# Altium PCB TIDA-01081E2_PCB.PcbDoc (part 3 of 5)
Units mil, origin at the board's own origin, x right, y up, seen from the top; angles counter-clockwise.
Board outline 8611.33 x 3169.64 mil, 4 copper layers (Top Layer, VCC, GND, Bottom Layer), stack 61.6 mil thick; 411 components, 187 nets, 1087 pads, 1987 vias.
Unrouted connection lines stored in the file: 7.
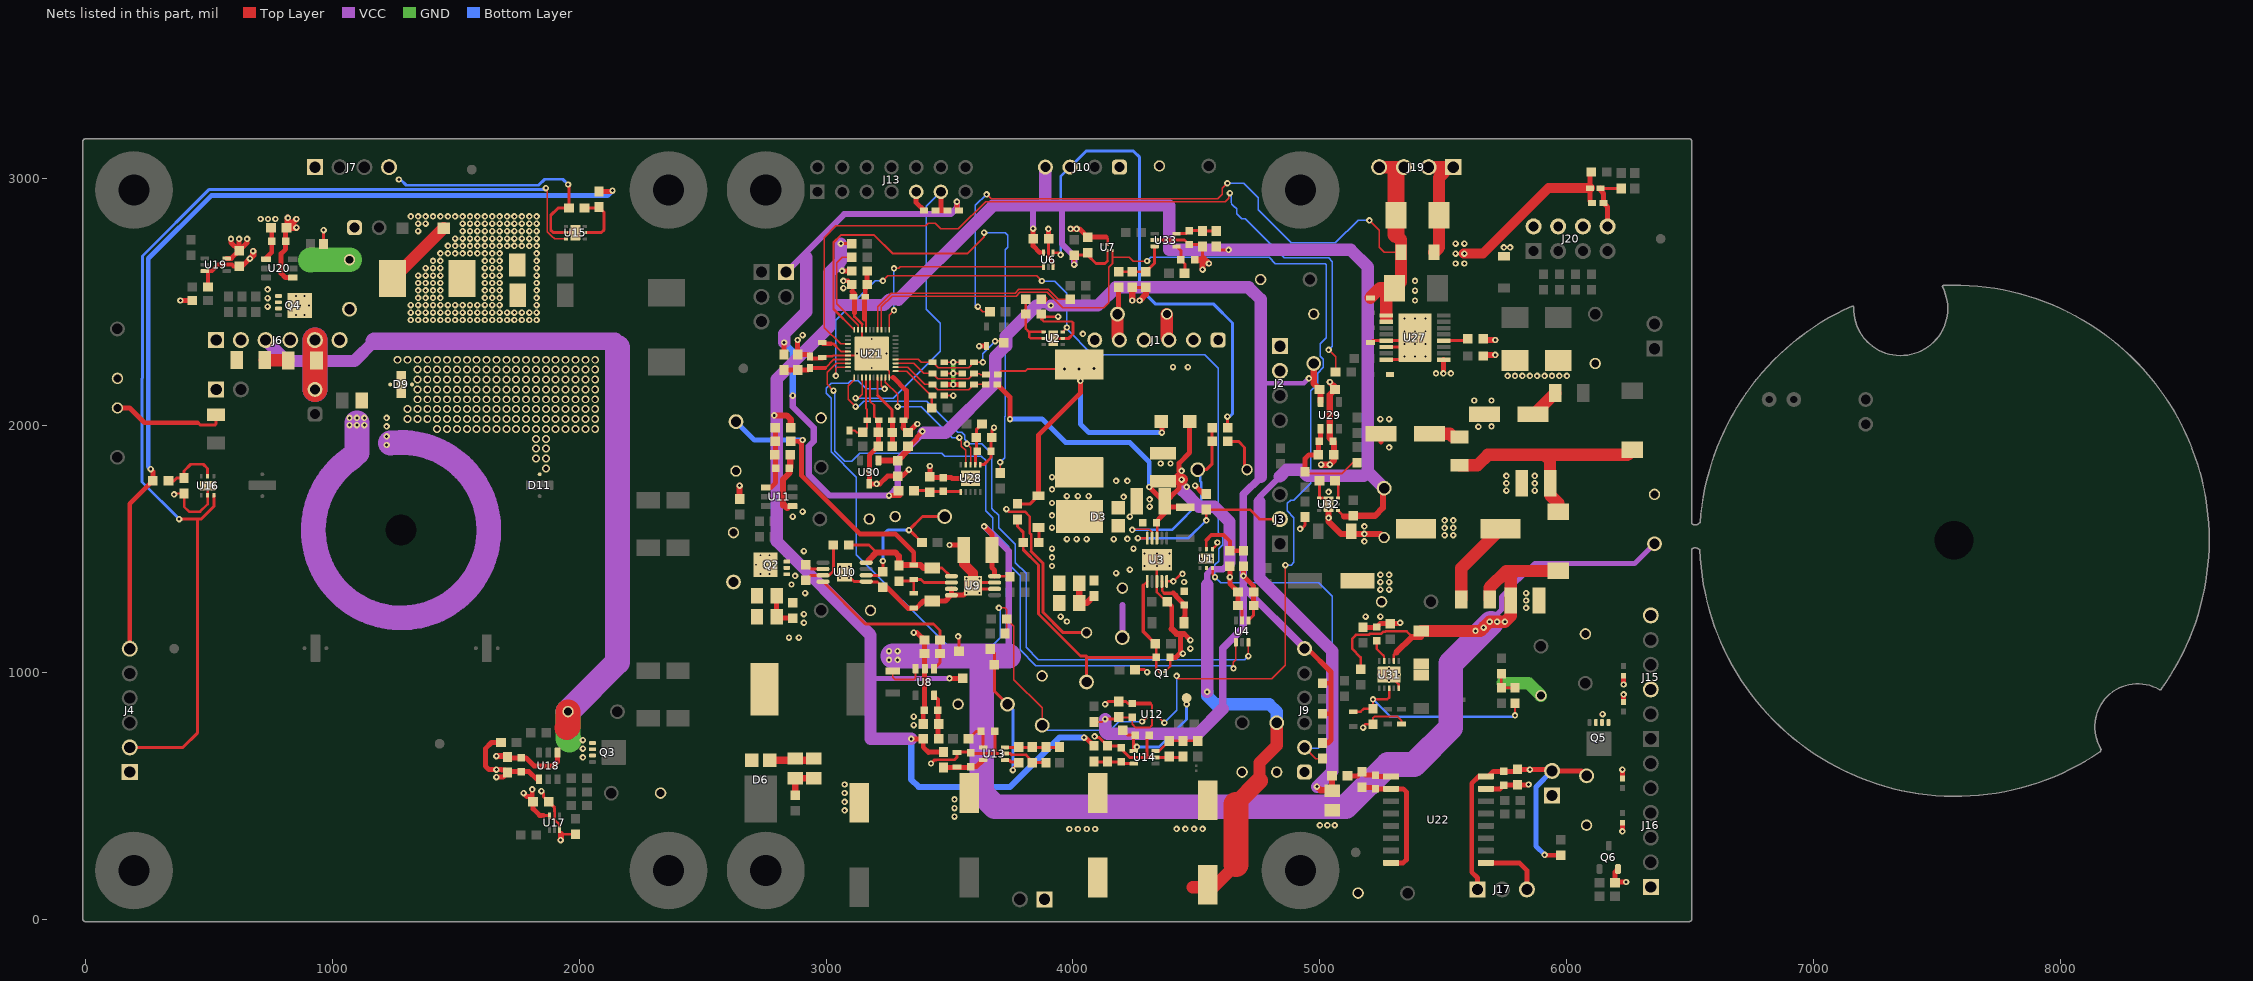
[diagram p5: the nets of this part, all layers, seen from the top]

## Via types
v1: diameter 32, hole 20, Top Layer to Bottom Layer, tented both sides, 779 vias
v2: diameter 26, hole 12, Top Layer to Bottom Layer, tented both sides, 622 vias
v3: diameter 24, hole 12, Top Layer to Bottom Layer, 506 vias
v4: diameter 19.68, hole 7.87, Top Layer to Bottom Layer, 50 vias
v5: diameter 26, hole 12, Top Layer to Bottom Layer, 14 vias
v6: diameter 19.68, hole 7.87, Top Layer to Bottom Layer, tented both sides, 12 vias
v7: diameter 19.68, hole 7.87, Top Layer to Bottom Layer, tented top, 4 vias

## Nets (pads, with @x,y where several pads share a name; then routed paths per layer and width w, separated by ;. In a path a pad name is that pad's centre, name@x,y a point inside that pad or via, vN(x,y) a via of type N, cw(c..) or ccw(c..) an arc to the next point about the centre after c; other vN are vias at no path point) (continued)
+3V3A: C10.1 C11.1 C39.2 C40.1 C78.1 C79.1 J4.6 J9.6 J12.1 R1.1 R2.1 R51.1 R55.1 R56.1 R71.2 R72.2 R73.2 R81.2 R82.2 R83.2 R110.1 TP20.1 U4.4 U12.5 U29.5 U30.1 | length 12363.1
  Top Layer w8: v2@2830,2325 v2(2830,2335) ; R51.1@4085,798.5 4118.5,798.5 v2(4130,810) ; C39.2@4185,818.5 4186.5,817 C40.1@4240,817 4240,790 4255,775 4310,775 4320,785 U12.5@4320,818.19
  Top Layer w12: v2(4130,810) 4176.5,810 C39.2@4185,818.5 ; U4.4@4710.59,1209.29 4731.5,1230.2 C10.1@4731.5,1270
  Top Layer w20: J4.6@180,1095 180,1681.5 R56.1@273.5,1775 273.5,1813.5 v2(265,1822.01) ; R55.1@2080,2946.5 2131.5,2946.5 v2(2135,2950) ; R82.2@2830,2286.5 v2@2830,2325 ; v2(3255,1715) 3298.5,1715 ; R81.2@3331.5,1915 3337.51,1915 3367.18,1944.67 3367.18,1950.69 3390,1973.5 v2(3390,1975) ; v2(3530,2905) 3530,2878.62 R83.2@3538.62,2870 ; R1.1@4690,1428.5 v2(4690,1390) 4731.5,1348.5 C11.1@4731.5,1325 C10.1@4731.5,1270 ; J9.6@4938,1095 4950,1095 5044.7,1000.3 5044.7,960 ; R73.2@5010,712.87 5032.87,712.87 5045,725 5044.7,725.3 5044.7,834 ; R72.2@5010,831.5 5042.2,831.5 5044.7,834 ; R71.2@5010,955.12 5039.82,955.12 5044.7,960 ; 5044.7,834 5044.7,960
  Top Layer w25: U30.1@3212.4,1857.24 3289.25,1857.24 C79.1@3290,1856.5 3331.5,1897.99 R81.2@3331.5,1915 ; R2.1@3871.5,2510 R2.1@3885,2510 ; TP20.1@4975,2250 4975,2168.5 C78.1@4998.5,2145 5002.6,2140.91 U29.5@5002.6,2094.13
  VCC w20: 4760.01,2169.99 4934.99,2169.99 v2(4955,2190)
  VCC w25: J12.1@2838,2620 3073,2855 3505,2855 3530,2880 v2(3530,2905) ; v2(2865,2120) 2865,2075 2950,1990 2950,1935 2930,1915 2930,1800 3015,1715 v2(3255,1715) 3290,1750 3290,1862.77 v2@3396.11,1968.89 ; 3851.46,2485 v2(3910,2485)
  VCC w30: 4606,851 4606,1096 4690,1180 4690,1345 ; 4760,1790 4690,1720 v2(4690,1390) 4690,1345 ; J9.6@4938,1097 4690,1345
  VCC w50: v2(2830,2335) 2830,2370 2920,2460 2920,2680 ; v2@3396.11,1968.89 3483.89,1968.89 3685,2170 3685,2277.77 3729,2321.77 3729,2358.23 3726.84,2360.38 3851.46,2485 ; v2(3910,2485) 4100,2485 4173.5,2558.5 4711.5,2558.5 4760,2510 4760,2170 4760,1790 ; v2(4130,810) 4130,760 4140,750 4505,750 4606,851 ; J9.6@4938,1095 J9.6@4938,1097
  Bottom Layer w20: v2(265,1822.01) 255,1832.01 255,2675 510,2930 2115,2930 v2(2135,2950)
  Bottom Layer w25: v2(2830,2335) 2865,2300 v2(2865,2120)
+5V0: C13.2 C14.2 C43.2 C44.2 C45.2 C46.2 C47.2 C48.2 C96.1 J7.4 J10.4 R19.1 R21.1 R29.2 R39.2 R40.2 R41.2 R80.2 R89.1 R96.2 R119.2 R125.2 R138.2 TP23.1 U6.5 U7.5 U17.5 U18.1 U19.5 U20.1 U32.1 | length 11889.1
  Top Layer w8: 4140,2665 U7.5@4140,2708.19
  Top Layer w12: 1855,420 1855.87,419.13 U17.5@1880.31,419.13 ; v2(3060,2735) R96.2@3103.5,2735 ; v2@3835,2800 v2(3838.5,2796.5) ; v2(4005,2650) R19.1@4005,2688.5 4060,2688.5 4093.5,2655 4130,2655 4140,2665 ; R125.2@4580,2723.5 4593.5,2710 v2(4630,2710) ; U32.1@5073.39,1654.41 5097.8,1630 5098,1630
  Top Layer w16: 3865.87,2699.13 U6.5@3880.31,2699.13
  Top Layer w20: U19.5@572.4,2675.59 591.53,2675.59 622.43,2706.5 C48.2@623.11,2706.5 ; v2(590,2755) 590,2739.6 C48.2@623.11,2706.5 ; v2(623.11,2755) C48.2@623.11,2706.5 ; v2(655,2755) 655,2738.39 C48.2@623.11,2706.5 ; U20.1@732.22,2672.4 732.22,2677.22 755.11,2700.11 C46.2@755.11,2745 755.11,2796.5 C47.2@751.61,2800 ; v2(1665,575) 1691.5,575 C44.2@1710,593.5 C44.2@1708.5,595 ; R89.1@1683.5,715 1645,715 1620,690 1620,620 1635,605 v2(1665,605) 1685,605 1686.65,603.35 1700.16,603.35 C44.2@1708.5,595 ; v2(1775,510) 1789,496 1802,496 1810,488 v2(1810,525) ; C45.2@1810,478.5 C45.2@1813.5,475 1813.5,446.5 1840,420 1855,420 ; U18.1@1837.6,565.87 1828.27,565.87 1797.13,597 C43.2@1765,597 1713.5,597 1711.5,595 C44.2@1708.5,595 ; v2(3065,2625) R80.2@3103.5,2625 ; v2(3345,730) R21.1@3393.5,730 3393.5,696.5 3415,675 3416.5,676.5 R39.2@3475.31,676.5 ; v2(3500,975) R41.2@3553.5,975 ; v2(3838.5,2796.5) C14.2@3838.5,2755 3838.5,2726.5 3865.87,2699.13 ; v2(4045,735) 4051.5,735 R40.2@4085,701.5
  Top Layer w25: v2(2790.14,2040) 2840.14,2040 2856.63,2023.5 R29.2@2856.63,1990 ; v5(4988,536) 5002.5,521.5 5050,521.5 5048.5,522.99 R138.2@5048.5,580 ; 5098,1630 5131.5,1630 R119.2@5135,1633.5 5223.5,1633.5 5255,1665 5255,1740 TP23.1@5260,1745
  VCC w20: 3060,2665 3065,2660 v2(3065,2625) ; 3180,970 3185,975 v2(3500,975)
  VCC w25: v2(3838.5,2796.5) 3838.5,2878.5 3850,2890 ; 3955,2890 3955,2735 4005,2685 v2(4005,2650) ; 4755,1690 4755,1709.1 4838,1792.1
  VCC w50: 3013.5,2487 3234.77,2487 3256.77,2509 3293.23,2509 3293.61,2508.61 3461,2676 3463.23,2676 3675,2887.77 3675,2890 3850,2890 3890,2890 ; v2(3060,2735) 3060,2665 3013.5,2618.5 3013.5,2400 2800,2186.5 2800,1530 3180,1150 3180,970 3180,730 v2(3345,730) ; J10.4@3888,3045 3888,2892 3890,2890 ; 4755,1690 4755,1380 5050,1085 5050,598 v5(4988,536) ; 4838,1792.1 4865.9,1820 4924.45,1820 4949.45,1795 5178,1795 5194,1811 ; TP23.1@5260,1745 5194,1811 ; 3890,2890 3955,2890 4390,2890 4390,2710 v2(4630,2710) 5125,2710 5194,2641 5194,1811
  Bottom Layer w25: v2(3345,730) 3345,565 3375,535 3745,535 3945,735 v2(4045,735)
  other v2: 710,2835 740,2835 770,2835
+6V63: C19.1 C20.1 R25.2 R28.2 R30.2 TP5.1 U9.1 U10.8 | length 1686.3
  Top Layer w12: R30.2@3091.5,1515 3174.21,1515 3204.21,1485 ; U10.8@3168.39,1443.39 U10.8@3162.6,1443.39 3171.85,1452.64 ; C20.1@3430,1421.93 3469.92,1421.93 3503.46,1388.39 U9.1@3507.4,1388.39
  Top Layer w20: R28.2@2856.63,1935 2890,1935 ; v2(2905,1940) 2900,1935 2890,1935 ; R25.2@3355,1434.53 3355,1485 3280,1560 3136.87,1560 2900.14,1796.73 2900.14,1924.86 2890,1935
  Top Layer w25: 3171.85,1452.64 3204.21,1485 3280,1485 3295,1470 C19.1@3295,1431.5 3298.03,1434.53 R25.2@3355,1434.53 3381.97,1434.53 3394.57,1421.93 C20.1@3430,1421.93
  Bottom Layer w20: TP5.1@2635,2014.65 2709.65,1940 v2(2905,1940)
+VDD_ISO: C64.2 C66.1 J14.2 J17.1 R87.2 TP30.1 U22.16 | length 1405
  Top Layer w20: J17.1@5638,120 5638,167 5615,190 5615,549.83 5642.59,577.41 U22.16@5671.93,577.41 5682.41,577.41 5703,598 C64.2@5745,598 5791.5,598 C66.1@5800,606.5 5848.5,606.5 v2(5850,605) 5940,605 J14.2@5945,600 ; v2(5910,260) 5911.5,258.5 R87.2@5975,258.5 ; J14.2@5940,600 J14.2@5945,600 ; J14.2@5955,590 J14.2@5945,600 ; TP30.1@6080,580 6060,600 J14.2@5945,600
  Bottom Layer w20: v2(5910,260) 5875,295 5875,535 J14.2@5940,600
\BUCK_&_BOOST_VOUT_OV_RESET: U7.6 U12.6 U21.13 | length 4649.5
  Top Layer w6: U21.13@3224.37,2386.46 3224.37,2479.37 3268,2523 3770.39,2523 3785.09,2537.7 3895.33,2537.7 3958.03,2475 4125,2475 4145,2495 4145,2640 4159.69,2654.69 ; 4159.69,2681.44 4161.12,2680 4228.77,2680 4243.77,2665 v2(4300,2665) ; U12.6@4339.69,818.19 4346.81,818.19 v2(4370,795) ; v2(4420,985) 4420,979.19 4425,974.19 4805.8,974.19 4860,1028.38 v2(4860,1433.45)
  Top Layer w8: 4159.69,2654.69 4159.69,2681.44 U7.6@4159.69,2708.19
  Bottom Layer w6: v2(4300,2665) 4315,2680 4794.09,2680 4820.09,2654 5022,2654 5026,2650 5026,2354.97 5001,2329.97 5001,2279.15 5014,2266.15 5014,2233.85 4991.15,2211 4991.15,2168.27 4963,2140.11 4963,1764.97 4895.03,1697 4880.89,1697 4868,1684.11 4868,1653 4895,1626 4895,1445 4883.45,1433.45 v2(4860,1433.45) ; v2(4370,795) 4420,845 v2(4420,985)
\DISCHG_L: J10.3 R15.2 U6.4 | length 2132.7
  Top Layer w10: U6.4@3919.69,2699.13 3940.87,2699.13 v2(3950,2690) v2@3950,2685
  Top Layer w12: v2(4625,2035) 4626.5,2033.5 R15.2@4626.5,1990
  Bottom Layer w10: v2(3950,2690) 3950,3007 J10.3@3988,3045
  Bottom Layer w12: J10.3@3988,3045 4053,3110 4245,3110 4270,3085 4270,2555 4335,2490 4570,2490 4646,2414 4646,2046 4635,2035 v2(4625,2035)
\RST: C62.1 J13.11 R83.1 U21.33 | length 1336.4
  Top Layer w6: v2(3120,2110) 3130,2110 3145.63,2125.63 U21.33@3145.63,2193.54
  Top Layer w20: C62.1@3443.62,2870 3465.79,2870 ; J13.11@3465,2945 3465,2870.79 3465.79,2870 ; R83.1@3491.38,2870 3465.79,2870
  Bottom Layer w6: v2(3120,2110) 3271.97,2110 3462,2300.03 3462,2413.97 3406,2469.97 3406,2886 J13.11@3465,2945
\SYNC_BUCK: U4.1 U21.28 | length 2913.5
  Top Layer w6: v2(3030,2140) 3005,2165 3005,2215 3040.63,2250.63 U21.28@3088.54,2250.63 ; v2(4650,1015) 4650,1040 4659.41,1049.41 U4.1@4659.41,1120.71
  Bottom Layer w6: v2(3030,2140) 3035,2135 3035,1895 3075,1855 3104.25,1855 3135.71,1886.46 3468.54,1886.46 3480.13,1874.87 3628.57,1874.87 3646,1857.44 3646,1653.95 3665.95,1634 3666.06,1634 3674.51,1625.54 3674.51,1572.51 3739.84,1507.19 3739.84,1436.22 3786,1390.06 3786,1090.06 3850.06,1026 4639,1026 v2(4650,1015)
\SYNC_EFUSE_&_BOOST: U21.39 U28.9 | length 561.3
  Top Layer w6: U21.39@3240.12,2193.54 3240.12,2174.88 3290,2125 v2(3290,2075) ; v2(3540,1950) 3540,1943.89 3547.82,1936.07 3547.82,1915.45 3565.31,1897.96 U28.9@3565.31,1840.12
  Bottom Layer w6: v2(3290,2075) 3385,2075 3508.63,1951.53 3510.16,1950 v2(3540,1950)
ALERT: J4.2 J9.2 R73.1 U1.3 U2.3 U15.3 U16.3 U21.29 | length 8907.4
  Top Layer w6: v2(1865,2960) 1870,2955 1870,2783.79 1888.79,2765 1890,2765 1900.59,2754.41 U15.3@1946.61,2754.41 ; v2(3040,2200) 3040,2230 3044.88,2234.88 U21.29@3088.54,2234.88 ; v2(3230,2585) 3250,2605 3852.95,2605 v2(3873.97,2583.97) ; U2.3@3958.39,2378.97 v2(3975.01,2395.59) ; J9.2@4938,695 4983.12,649.88 R73.1@5010,649.88
  Top Layer w10: U1.3@4565.59,1421.61 4565.59,1394.41 v2(4575,1385)
  Top Layer w12: J4.2@180,695 395,695 455,755 455,1620 ; v2(380,1620) 455,1620 ; U16.3@520.59,1716.61 520.59,1670.59 470,1620 455,1620
  Bottom Layer w6: v2(3040,2200) 3040,2425 3200,2585 v2(3230,2585) ; v2(3873.97,2583.97) 3926.03,2583.97 3975.01,2534.99 v2(3975.01,2395.59) 3975.01,2391.18 3973.83,2390 4077.86,2285.97 4532.97,2285.97 4589,2229.94 4589,1565 4607,1547 4607,1515.89 4590,1498.89 4590,1450 4575,1435 v2(4575,1385) 4598,1362 4994.97,1362 5050,1306.97 5050,750 4992.5,692.5 4940.5,692.5 J9.2@4938,695
  Bottom Layer w12: v2(380,1620) 230,1770 230,2190 231.13,2191.13 231.13,2684.89 500.11,2953.87 1858.87,2953.87 v2(1865,2960)
BOOST_VOUT/BUCK_VIN: C5.1 C6.1 C25.1 C28.1 C91.1 D1.1 J21.1 R3.2 R74.2 TP7.1 U3.8 | length 3854
  Top Layer w10: U3.8@4340,1542.6 4340.91,1543.5 4340.91,1620 4348,1620
  Top Layer w20: R74.2@3693.62,2165 3744.31,2114.31 3745,2115 v2(3745,2025) ; v2(4308.82,1749.68) 4368.5,1690 4377.09,1690 4395,1707.91 4395,1710 4430,1745 4430,1765 ; 4348,1620 4377.09,1649.09 4377.09,1665 4380.08,1667.99 R3.2@4455,1667.99 ; C5.1@4365,1772.91 4397.91,1772.91 v2(4440,1815) ; v2@4430,1815 4430,1846.57 4472.09,1888.66 D1.1@4472.09,2015
  Top Layer w50: 4426.55,1780 v2(4440,1780) ; 4485,128.74 4568.74,128.74 4660,220 ; 4755,560 4755,633 4825,703 TP7.1@4825,795
  Top Layer w70: 4660,465 4755,560
  Top Layer w100: 4660,220 4660,465
  VCC w25: 4543.5,1353.5 4543.5,1398.05 4561.95,1416.5 4607.5,1416.5 4634,1443
  VCC w50: 4445,1735 4510,1670 4572.91,1670 4634,1608.91 4634,1443 ; v2(4543.5,920) 4543.5,1353.5
  Bottom Layer w20: v2(3745,2025) 3875,2025 3970,1930 4230,1930 4308.82,1851.18 v2(4308.82,1749.68)
  Bottom Layer w50: v2(4543.5,920) 4543.5,903.5 4577,870 4795,870 4825,840 TP7.1@4825,795
  other v2: 4460,1750
BOOST_VOUT_CTRL: R38.2 R45.1 R54.2 TP10.1 U13.1 | length 635.7
  Top Layer w12: R38.2@3665,1093.5 3681.5,1077.01 R45.1@3681.5,1030 3681.5,923.5 TP10.1@3735,870 ; U13.1@3724.61,644.41 3741.38,644.41 3750.31,635.47 3780.31,635.47 3756.69,611.85 v2(3756.69,603.31)
  Bottom Layer w6: TP10.1@3728.89,870 TP10.1@3735,870
  Bottom Layer w12: TP10.1@3735,870 3756.69,848.31 v2(3756.69,603.31)
BOOST_VOUT_OVP: R37.2 R44.2 TP11.1 U12.4 U21.38 | length 2996.7
  Top Layer w6: U21.38@3224.37,2193.54 3224.37,2159.52 v2(3236.89,2147) ; v2(3700,1260) 3723.45,1260 3731.5,1251.95 R44.2@3731.5,1215 ; R37.2@3725,1156.5 3731.5,1162.99 R44.2@3731.5,1215 ; TP11.1@3875,785 3875,855 3760,970 3760,1186.5 R44.2@3731.5,1215 ; v2@4280,795 v2@4280,797.87 ; v2(4280,800) v2@4280,797.87 ; U12.4@4300.31,818.19 v2@4280,797.87
  Bottom Layer w6: v2(3236.89,2147) 3163,2147 3130,2180 3100.59,2180 3090.59,2170 3020,2170 3000,2150 3000,2130 3020,2110 3020,1893.03 3123,1790.03 3123,1475.89 3492.59,1106.3 3672.6,1106.3 3706.3,1140 3706.3,1253.7 v2(3700,1260) ; TP11.1@3875,785 3895,765 4151.3,765 4186.3,800 v2(4280,800)
BUCK_DISCHG_COFF: R60.2 U21.20 | length 2161.5
  Top Layer w6: R60.2@3705,1806.5 v2(3705,1850)
  Top Layer w8: U21.20@3114.13,2386.46 3030,2470.59 3030,2740 3060,2770 3195,2770 3269,2696 3573.37,2696 3640,2762.63 v2(3640,2780)
  Bottom Layer w6: v2(3640,2780) 3725,2780 3735,2770 3735,2720 3725,2710 3725,2036.11 3723,2034.11 3723,1868 v2(3705,1850)
BUCK_OFF: U6.1 U21.11 | length 864.2
  Top Layer w6: U21.11@3255.87,2386.46 3255.87,2445.87 v2(3275,2465) ; v2(3275,2635) 3295,2635 3300.87,2640.87 U6.1@3880.31,2640.87
  Bottom Layer w6: v2(3275,2465) 3275,2605 v2(3275,2635)
BUCK_ON: R12.2 R15.1 TP3.1 U3.9 | length 793.9
  Top Layer w6: v2(4240,1576.03) 4242.15,1578.17 4306.8,1578.17 4308.95,1576.03 4310,1576.03 4320.31,1565.71 U3.9@4320.31,1542.6
  Top Layer w12: TP3.1@4495,1820 TP3.1@4505,1820 4540,1820 4563.5,1843.5 R12.2@4563.5,1935 R15.1@4563.5,1990
  Bottom Layer w10: v2(4240,1576.03) 4401.03,1576.03 4519,1694 4519,1768.94 4515,1772.94 4515,1810 TP3.1@4505,1820
BUCK_VOUT: D1.2 D5.2 J1.4 J1.5 J1.6 L1.2 R9.2 R13.2 R75.2 TP2.1 | length 1809.2
  Top Layer w8: R75.2@3695,2205 3710,2220 3807.99,2220 3816.5,2228.5 v2(4025,2228.5)
  Top Layer w12: R9.2@3775,1681.5 3827.03,1681.5 D5.2@3860,1714.47
  Top Layer w20: D5.2@3860,1714.47 3860,1960 4030,2130 v2(4030,2180) 4030,2223.5 v2(4025,2228.5) ; TP2.1@4180,2450 4185,2455 R13.2@4185,2558.5 ; D1.2@4357.91,2015 4360,2012.91 v2(4360,1970)
  Top Layer w50: TP2.1@4180,2450 4180,2353.11 J1.5@4188.11,2345
  Bottom Layer w20: v2(4030,2180) 4030,2005 4065,1970 v2(4360,1970)
  other v2: 3965,2228.5 4085,2230 4040,2370
BUCK_VOUT_OV: R14.1 U21.14 | length 919.1
  Top Layer w6: U21.14@3208.62,2386.46 3208.62,2480.59 3263.03,2535 3765.42,2535 3780.12,2549.7 3900.3,2549.7 3940,2510 R14.1@3988.5,2510
DIN: U4.3 U21.31 U28.8 | length 2724.5
  Top Layer w6: U21.31@3114.13,2193.54 3114.13,2184.13 3090,2160 3090,2105 v2(3120,2075) ; v2(3569.82,1924.56) 3585,1909.38 U28.8@3585,1840.12 ; v2(4710,1065) 4710,1120.12 U4.3@4710.59,1120.71
  Bottom Layer w6: v2(3120,2075) 3130,2075 3152,2097 3407.75,2097 3532.75,1972 3549.11,1972 3562,1959.11 3562,1942.75 3575,1929.75 v2(3569.82,1924.56) 3630.44,1924.56 3670,1885 3670,1663.89 3675.89,1658 3676,1658 3699,1635 3699,1584.23 3766.1,1517.13 3766.1,1443.9 3810,1400 3810,1100 3860,1050 4695,1050 v2(4710,1065)
EFUSE_IMON: C49.1 R100.2 U21.1 | length 247.2
  Top Layer w6: U21.1@3281.46,2219.13 3325.87,2219.13 3425,2120 C49.1@3431.38,2120
  Top Layer w10: R100.2@3428.5,2065 3428.5,2117.13 C49.1@3431.38,2120
EFUSE_OK: R97.2 U21.19 | length 377.1
  Top Layer w6: R97.2@3103.5,2680 3065,2680 3043,2658 3043,2492 3129.88,2405.12 U21.19@3129.88,2386.46
EFUSE_ON: R99.1 U21.23 | length 3260.5
  Top Layer w6: U21.23@3088.54,2329.37 3058.66,2329.37 2993,2395.03 2993,2759.97 3040.03,2807 3403,2807 3413,2817 3443,2817 3465,2795 3536.06,2795 3646.06,2905 4616.03,2905 4630,2918.97 4630,2935 v2(4635,2940) ; v2(5035,2305) 5063.5,2276.5 R99.1@5063.5,2215
  Bottom Layer w6: v2(4635,2940) 4640,2935 4640,2900 4643,2897 4643,2895.89 4655.89,2883 4657,2883 4664.08,2875.92 4664.08,2855.92 4684,2836 4698.14,2836 4856.14,2678 5035.03,2678 5050,2663.03 5050,2320 v2(5035,2305)
EFUSE_VIN: C67.1 D17.1 D18.2 J19.3 J19.4 R94.2 R137.2 U27.1 U27.2 | length 3421.8
  Top Layer w6: v5(3615,2480) 3635,2460 R137.2@3663.5,2460 ; v2(3650,2935) 3668,2917 4587,2917 4605,2935 4605,2960 v2(4625,2980) ; v5(5200,2830) 5240,2790 5240,2720 5260,2700 C67.1@5328.07,2700
  Top Layer w12: U27.2@5268.86,2418.98 U27.1@5268.86,2444.57
  Top Layer w50: R94.2@5205,2516.5 5243.5,2555 D17.1@5302.99,2555 ; J19.4@5240,3045 J19.3@5340,3045 5307.99,3012.99 ; 5268.86,2435.25 5268.86,2520.87 D17.1@5302.99,2555 ; 5307.99,2772.01 5328.07,2751.93 C67.1@5328.07,2700 5328.07,2580.08 D17.1@5302.99,2555
  Top Layer w70: 5307.99,2772.01 D18.2@5307.99,2850 5307.99,3012.99
  Bottom Layer w6: v5(3615,2480) 3610,2480 3605,2485 3605,2890 v2(3650,2935) ; v2(4625,2980) 4691.97,2980 4750,2921.97 4750,2871.66 4883.66,2738 5062.91,2738 5154.91,2830 v5(5200,2830)
FILTER_OUT: C21.1 C69.1 C84.1 L4.2 R20.1 R24.1 R93.2 R116.2 TP16.1 U8.3 U9.8 U31.2 | length 6982.7
  Top Layer w6: 5650,1166.93 5650,1201.62 ; TP16.1@6329.47,1517 TP16.1@6355.74,1490.74
  Top Layer w8: R20.1@3270,1004.29 3270,980 3280,970 3355,970 3362.6,977.6 U8.3@3362.6,1014.13
  Top Layer w10: U9.8@3682.6,1388.39 3743.11,1388.39 R24.1@3745,1386.5 ; R116.2@5165,1011.5 5165,1060 5130,1095 5130,1135 5145.81,1150.81 5198.26,1150.81 5202.45,1155 5247.56,1155 5256.75,1164.19 5265.49,1164.19 5266.3,1165 5351.5,1165 5374.57,1141.93 ; U31.2@5299.69,1045.12 5299.69,1069.69
  Top Layer w12: 5299.69,1069.69 5310,1080
  Top Layer w20: v2(3640,1590) 3672.09,1557.91 C21.1@3672.09,1495 3672.09,1422.91 3682.6,1412.4 U9.8@3682.6,1388.39 ; 5371.93,1141.93 5374.57,1141.93
  Top Layer w25: 5310,1080 5371.93,1141.93 ; 5374.57,1141.93 5410,1141.93
  Top Layer w50: C84.1@5410,1166.93 v2(5630,1166.93) 5650,1166.93 v2(5663.07,1180) v2(5687.09,1204.02) v2(5749.02,1204.02) 5772.91,1227.91 C69.1@5772.91,1290 5772.91,1391.93 5754.92,1409.92 ; R93.2@5687.09,1295 5687.09,1342.09 5754.92,1409.92 ; L4.2@5965,1409.92 5754.92,1409.92
  VCC w20: v2(5687.09,1204.02) 5735,1251.93 5735,1305 5870,1440 6275,1440 TP16.1@6355,1520
  VCC w25: v2(3640,1590) 3740,1490 3740,1065
  VCC w100: 3270,1065 3629.98,1065 ; 3740,1065 3629.98,1065 ; v2@5693.05,1198.05 5530,1035 5530,775 5381,626 5276.01,626 5105.01,455 3684.32,455 3629.98,509.34 3629.98,1065
  other v2: 3255,1050 3290,1050 3255,1085 3290,1085 5718.05,1204.02
GND: C1.2 C2.2 C3.2 C5.2 C6.2 C7.2 C8.2 C9.2 C10.2 C11.2 C12.1 C13.1 C14.1 C15.2 C16.2 C17.1 C20.2 C21.2 C22.1 C23.1 C24.2 C25.2 C26.2 C27.2 C28.2 C29.2 C30.2 C31.1 C32.1 C33.1 C34.1 C35.2 C36.2 C37.1 C38.1 C39.1 C40.2 C41.2 C42.2 C43.1 C44.1 C45.1 C46.1 C47.1 C48.1 C49.2 C50.2 C51.2 C52.2 C53.2 C54.1 C55.2 C56.2 C57.1 C58.2 C59.1 C60.2 C61.1 C62.2 C63.1 C65.2 C67.2 C68.2 C69.2 C70.2 C71.2 C72.2 C74.1 C75.1 C76.1 C77.1 C78.2 C79.2 C80.2 C81.1 C82.2 C84.2 C86.2 C87.2 C88.1 C89.2 C90.2 C91.2 C92.1 C93.2 C94.1 C96.2 D3.1 D3.2 D18.1 D19.2 D20.2 D21.2 D23.2 D24.2 J1.1 J1.2 J1.3 J2.1 J2.2 J4.1 J6.1 J6.2 J6.3 J7.1 J8.1 J9.1 J10.1 J13.9 J19.1 J19.2 Q1.2@4371.89,1001.89 Q2.1 Q2.2 Q2.3 Q3.1 Q3.2 Q3.3 Q4.1 Q4.2 Q4.3 R6.1 R12.1 R16.1 R27.1 R33.1 R36.1 R50.1 R52.1 R53.1 R59.1 R65.1 R66.1 R67.2 R76.1 R77.1 R79.1 R90.1 R107.1 R108.1 R120.1 R121.1 R122.1 R123.1 R124.1 R130.1 TP1.2 TP2.2 TP3.2 TP4.2 TP5.2 TP6.2 TP7.2 TP8.2 TP9.2 TP10.2 TP11.2 TP12.2 TP13.2 TP14.2 TP15.2 TP16.2 TP17.2 TP18.2 TP19.2 TP20.2 TP21.2 TP22.2 TP23.2 TP24.2 TP26.2 TP27.2 TP28.2 TP29.2 U1.2 U1.4 U1.7@4540,1460 U2.2 U2.7@3920,2352 U3.3 U3.11 U4.5 U6.3 U7.2 U8.2 U9.3 U9.4 U9.6 U9.7 U9.9 U10.2 U10.5 U10.9 U11.4 U12.2 U13.2 U14.2 U15.2 U15.7@1985,2780 U16.2 U16.7@495,1755 U17.3 U18.4 U19.3 U20.4 U21.18 U21.26 U21.35 U21.40 U21.41 U22.2 U22.8 U27.9 U28.6 U28.11 U29.2 U30.3 U31.10 U31.11@5280,990 U32.4 U32.7@5035,1680 U33.2 | length 19046.4
  Top Layer w6: Q1.2@4371.89,1001.89 4393,1023
  Top Layer w8: C61.1@2927.13,2286.5 C61.1@2935,2278.62 C61.1@2943.62,2270 ; 3025,2280 3027.13,2282.13 U21.26@3088.54,2282.13 3177.13,2282.13 v4(3185,2290) ; C56.2@3103.5,2570 3111.38,2562.13 3111.38,2535.28 ; 3145.63,2409.37 U21.18@3145.63,2386.46 3145.63,2329.37 v4(3185,2290) ; U21.35@3177.13,2193.54 3177.13,2097.87 3195,2080 ; 3271.46,2193.54 U21.40@3255.87,2193.54 3255.87,2219.13 v4(3185,2290) ; C49.2@3478.62,2120 v2(3515,2120) ; C51.2@3478.62,2210 v2(3515,2210) R77.1@3551.38,2210 ; C52.2@3478.62,2255 v2(3515,2255) R79.1@3546.38,2255 ; 4312,873 4320,865 U12.2@4320,841.81 ; R121.1@5215,788.5 5215,815 5220,820 5315,820 5330,805 R120.1@5330,788.5
  Top Layer w10: v2(360,1720) 363.5,1723.5 C42.2@400,1723.5 400,1670 420,1650 465,1650 495,1680 U16.2@495,1716.61 U16.7@495,1755 ; U19.3@483.82,2624.41 U19.3@496.5,2624.41 ; 1900.91,436.51 1900.91,401.75 1919.68,382.97 U17.3@1919.68,360.87 1919.68,350.32 1926.5,343.5 R59.1@1985,343.5 ; C55.2@2985,2275 2990,2280 3025,2280 ; 3115,2455 3115,2440 3145.63,2409.37 ; 3195,2080 3195,2034.37 C54.1@3211.5,2017.87 ; 3446.77,645 3446.96,645.19 3520.19,645.19 ; v2(3730,1660) 3740,1650 3805,1650 3824.98,1630.02 3824.98,1562.96 3830,1557.95 3830,1489.26 ; 3751.18,665 3810,665 3835,640 C37.1@3835,633.5 ; v2(3900,2795) v2@3901.5,2793.5 ; U6.3@3919.69,2640.87 3919.69,2660.31 ; v2(3940,2440) 3885,2440 3877.95,2432.95 3874.45,2432.95 3871.5,2430 3881.5,2420 3995,2420 4000,2415 ; U7.2@4140,2731.81 4140,2755 ; U3.11@4340,1455 v6(4340,1429.41) U3.3@4340,1367.4 4340,1323.54 4378.54,1285 C3.2@4381.5,1285 ; 4393,1023 C9.2@4393,1060 ; U1.4@4565.59,1498.39 4585,1517.8 v2(4585,1525) ; v2(5175,775) 5175,780 5183.5,788.5 R121.1@5215,788.5 ; U31.11@5280,990 5319.37,950.63 U31.10@5319.37,934.88
  Top Layer w12: 455,2010 456.11,2010 466.11,2000 524.31,2000 529,2004.69 R67.2@529,2042.09 ; 594.56,2650 601.06,2643.5 ; C48.1@623.11,2643.5 C48.1@635.15,2643.5 ; R90.1@965,2734.31 v2(965,2790) ; v2(1847.03,517.97) v2@1854.06,510.94 ; v2@1855,510.94 1855,496.5 C45.1@1876.5,475 1900.91,450.59 1900.91,436.51 ; v2(1955,2975) 1958.5,2971.5 C41.2@1958.5,2880 1915,2880 1885,2850 1885,2790 1895,2780 U15.2@1946.61,2780 U15.7@1985,2780 ; C24.2@2920,1436.5 2938.7,1417.8 U10.2@2987.4,1417.8 ; U10.9@3062.2,1417.8 v4(3075,1405) 3113.39,1366.61 U10.5@3162.6,1366.61 3164.21,1365 3208.5,1365 R107.1@3230,1343.5 ; C59.1@3313.62,2020 C59.1@3325,2031.38 ; v2(3355,1160) 3368.5,1160 ; C17.1@3393.5,841.5 C17.1@3397,845 C17.1@3398.5,846.5 ; v2(3425,630) 3440,645 3446.77,645 ; 3520.19,645.19 3530.31,655.32 3530.31,676.5 3581.82,676.5 C33.1@3585.31,673 3588.31,670 3680.31,670 ; v2(3535,1145) 3538.5,1141.5 R50.1@3538.5,1085 ; C21.2@3537.91,1515 C21.2@3557.91,1495 3557.91,1438.11 ; U28.6@3624.37,1840.12 3638.74,1840.12 3668,1869.38 C74.1@3668,1895 3668,1946.5 C75.1@3671.5,1950 3671.5,1981.5 v2(3680,1990) ; U9.6@3682.6,1337.2 3607.8,1337.2 v4(3595,1350) 3607.8,1362.8 U9.7@3682.6,1362.8 ; C35.2@3683.32,760 3683.32,673 3680.31,670 ; 3751.18,665 3746.18,670 U13.2@3724.61,670 3680.31,670 ; 3830,1489.26 3878,1441.26 3878,1242.46 3960.46,1160 TP4.2@4055,1160 ; C37.1@3835,633.5 R52.1@3890.31,633.5 ; C14.1@3901.5,2755 3901.5,2678.5 3919.69,2660.31 ; U2.7@3920,2352 U2.2@3958.39,2352 3983.09,2352 4000,2368.91 4000,2385.22 ; 4000.01,2385.24 4000.01,2405.95 4000,2415 ; v2@4090,740 4089.82,740.18 v2(4087.59,740.18) 4092.77,735 4106.5,735 4108.31,733.18 4108.67,733.18 4140,701.85 C32.1@4140,701.5 4186.5,701.5 C34.1@4195,693 4195,689 4229,655 4309.69,655 ; v2(4130,870) 4141.5,881.5 C39.1@4185,881.5 4214.77,881.5 4223.27,873 C40.2@4240,873 ; 4133.5,2761.5 4140,2755 ; R16.1@4240,2558.5 C94.1@4295,2558.5 ; R6.1@4251.5,1010 4290,1010 v2(4300,1000) ; C36.2@4308,745 4300,737 4300,664.68 4309.69,655 ; U33.2@4330.71,2750 4452,2750 C92.1@4470,2732 4516.5,2732 C12.1@4525,2723.5 4525,2675 4520,2670 ; R53.1@4445,658.5 4441.5,655 U14.2@4334.29,655 4309.69,655 ; R12.1@4626.5,1935 4670,1935 4695,1910 TP3.2@4695,1820 ; C10.2@4668.5,1270 4685,1253.5 U4.5@4685,1209.29 ; v2(4920,1580) 4925,1580 4940,1595 R124.1@4940,1628.5 ; C90.2@4998.5,1775 4998.5,1707.48 U32.4@4996.61,1705.59 5009.41,1705.59 U32.7@5035,1680
  Top Layer w16: U19.3@483.82,2624.41 512.52,2624.41 538.11,2650 594.56,2650 ; R65.1@496.5,2560 U19.3@496.5,2624.41 ; 601.06,2643.5 C48.1@623.11,2643.5 ; C61.1@2943.62,2270 C55.2@2985,2270 ; C40.2@4240,873 4312,873
  Top Layer w20: TP13.2@130,2070 180,2070 240,2010 455,2010 ; v2(385,2505) R66.1@433.5,2505 ; C48.1@635.15,2643.5 v2(666.65,2675) ; C47.1@811.11,2796.5 C46.1@811.11,2745 811.11,2713 793.11,2695 793.11,2615 810.51,2597.6 U20.4@840.49,2597.6 ; C44.1@1713.5,653 C43.1@1765,653 1784.51,653 1817.51,620 1895,620 1912.4,637.4 U18.4@1912.4,674.13 ; v2(2885,2345) C60.2@2885,2286.5 C61.1@2927.13,2286.5 ; v2(3070,2585) 3088.5,2585 C56.2@3103.5,2570 ; 3105,2541.65 3111.38,2535.28 3115,2531.65 3115,2455 ; C54.1@3211.5,2017.87 C53.2@3211.5,1971.3 C80.2@3211.5,1915 3175,1878.5 U30.3@3175,1762.76 3217.76,1762.76 3248.5,1793.5 C79.2@3290,1793.5 3308.5,1793.5 v2(3335,1820) ; R107.1@3230,1343.5 3246.5,1343.5 3331.5,1258.5 3365,1258.5 3394.57,1288.07 C20.2@3430,1288.07 3483.86,1288.07 U9.4@3507.4,1311.61 ; 3271.46,2193.54 3325,2140 C59.1@3325,2031.38 ; C59.1@3313.62,2020 3313.62,1992.13 3311.5,1990 C58.2@3331.5,1970 3366.5,2005 v2(3370,2005) ; J13.9@3365,2945 3365,2901.38 C62.2@3396.38,2870 ; 3368.5,1160 R33.1@3398.5,1130 C17.1@3398.5,846.5 ; C16.2@3393.5,790 C17.1@3393.5,841.5 ; v2(3420,1835) C77.1@3420,1791.5 3423.5,1788 C76.1@3475,1788 3507,1788 3510,1785 v7(3557.44,1785) U28.11@3585,1785 ; C50.2@3478.62,2165 v2(3515,2165) R76.1@3551.38,2165 ; v2(3500,1515) C21.2@3537.91,1515 ; U9.3@3507.4,1337.2 U9.4@3507.4,1311.61 ; v4(3595,1350) 3556.61,1311.61 U9.4@3507.4,1311.61 ; v5(3620,2320) 3620.63,2320.63 D24.2@3650,2320.63 ; C14.1@3901.5,2755 v2@3901.5,2793.5 ; v2(3990,2795) v2(4015,2795) 4026.5,2795 C13.1@4060,2761.5 4133.5,2761.5 ; C3.2@4381.5,1285 4400,1266.5 4400,1175.16 ; C9.2@4393,1060 4417,1060 4435,1078 4435,1140.16 ; 4450,1155 v2(4475,1130) ; v2(4495,1755) 4528.5,1721.5 C8.2@4540,1721.5 ; C1.2@4635,1428.5 v2(4635,1385) 4635,1358.5 C11.2@4668.5,1325 C10.2@4668.5,1270 ; C65.2@5170,533.5 5219.32,533.5 5225.41,527.41 U22.2@5288.07,527.41 5337.59,527.41 5350,515 5350,240 5337.41,227.41 U22.8@5288.07,227.41 ; R122.1@5175,1181.5 5228.5,1181.5 C88.1@5230,1183 5243.5,1196.5 5321.5,1196.5 v2(5325,1200) ; 5246.57,1932.57 C71.2@5246.57,1965 ; v2(5500,2210) 5501.14,2211.14 U27.9@5501.14,2265.43 ; R108.1@6098.5,3025 6093.35,3019.84 D23.2@6093.35,2960 6093.35,2908.03 C15.2@6101.38,2900
  Top Layer w25: v2(666.65,2675) 680,2688.35 v2(680,2705) ; C47.1@811.11,2796.5 C47.1@814.6,2800 C47.1@820,2800 ; C47.1@820,2805.4 v2(820,2840) ; v2(855,2800) C47.1@820,2800 ; v2(855,2835) C47.1@820,2800 ; v2(1665,660) 1706.5,660 C44.1@1710,656.5 ; v2(1925,320) 1926.5,321.5 1926.5,343.5 ; R36.1@2650,1701.5 v2(2650,1755) ; 2842.56,1664.55 2831.16,1675.95 2825.95,1675.95 2825.95,1780.78 2852.37,1807.2 ; C22.1@2851.5,1825 2855,1828.5 C23.1@2855,1880 ; v2(4240,2505) R16.1@4240,2558.5 ; v2(4270,2505) 4295,2530 C94.1@4295,2558.5 ; 4400,1175.16 4420.16,1155 4450,1155 ; C93.2@4493,2670 4520,2670 ; v2(4525,2630) 4525,2675 4530,2675 v2(4550,2655) ; v2(5005,1840) v2(5040,1840) 5056.5,1856.5 C82.2@5056.5,1880 5056.5,1931.5 C81.1@5053,1935 5040,1948 U29.2@5040,1985.87 5040,2123.5 C78.2@5061.5,2145 5061.5,2153.5 v2(5040,2175) ; U32.7@5035,1680 v4(5035,1658.35) 5035,1610 5085,1560 5245,1560 TP23.2@5260,1545
  Top Layer w40: 3557.91,1438.11 3595,1401.02 v4(3595,1350) ; v2@5582.01,2695 5660,2695 5925,2960 D23.2@6093.35,2960
  Top Layer w50: TP2.2@4380,2450 4380,2353.11 J1.3@4388.11,2345 ; J19.2@5440,3045 5524.02,3045 5482.01,3002.99 D18.1@5482.01,2850 5482.01,2720.08 C67.2@5461.93,2700
  Top Layer w100: 1950,775 1955,780 TP26.2@1955,840
  VCC w50: J6.3@730,2345 815,2260 1090,2260 1170,2340 ; 2145,1915 2155,1905
  VCC w70: 1170,2340 2145,2340
  VCC w100: TP26.2@1955,840 2155,1040 2155,2315
  GND w20: v2(3515,2165) v2(3515,2210) v2(3515,2255)
  GND w50: 5740,955 5845,955 TP18.2@5895,905
  GND w100: 911.57,2668.38 913.19,2670 TP27.2@1070,2670 ; TP26.2@1955,840 1955,730 1960,725
  Bottom Layer w12: v2(1270.16,2995) 1276.87,2995 1300,2971.87 1835.87,2971.87 1860.2,2996.2 1933.8,2996.2 v2(1955,2975)
  other v2: 3985,364.63 4020,364.63 4055.63,364.63 4090,364.63 4420,365 4455,365 4490.63,365 4525,365 5000,380 5030,380 5060,380 3520,415 3075,440 3520,449.37 3075,475 3520,485 3075,510.63 3075,545 2015,655 2015,690 2015,725 3355,785 3355,820 4445,1075 4475,1095 2850,1140 2890,1140 2910,1200 5185,1225 5245,1225 2910,1235 5835,1260 5835,1290 2915,1320 5835,1320 5245,1334.37 5280,1334.37 2860,1355 5245,1364.37 5280,1364.37 2875,1390 5245,1394.37 5280,1394.37 4175,1401.1 4230,1415 2910,1490 4245,1500 5180,1530 4165,1538.9 4220,1540 5505,1554.37 5540,1554.37 5180,1560 5505,1584.37 5540,1584.37 5180,1590 5505,1614.37 5540,1614.37 5035,1625 2865,1630 4230,1630 2905,1650 4310,1670 4310,1700 4205,1710 5035,1730 5755,1735 5870,1735 3205,1762.76 5755,1765 5870,1765 4175,1775 4220,1775 5755,1795 5870,1795 3175,1815 4355,1845 4395,1845 5280,1910 5641.35,1993.78 5695,1995 5245,2025 5280,2025 5625,2100 5695,2100 5760,2200 5790,2200 5820,2200 5850,2200 5880,2200 5910,2200 5940,2200 5970,2200 6000,2200 5470,2210 5530,2210 4405,2235 4465,2235 2905,2365 738.11,2480 738.11,2515 738.11,2550 3070,2555 5550,2655 5585,2655 5550,2695 5585,2695 5550,2735 5585,2735
  other v4: 5280,965.39 5240.63,990 5319.37,990 5280,1014.61 3567.83,1320.87 3622.17,1320.87 3567.83,1379.13 3622.17,1379.13 3057.28,1381.38 3092.72,1381.38 3057.28,1428.62 3092.72,1428.62 4518.35,1460 4561.65,1460 5035,1701.65 3185,2230.94 3125.94,2290 3244.06,2290 3185,2349.06
  other v6: 4288.82,1429.41 4391.18,1429.41 4288.82,1480.59 4340,1480.59 4391.18,1480.59
  other v7: 3585,1765.32 3612.56,1785 3585,1804.68
GND_ISO: C64.1 C66.2 J14.1 J15.3 J15.6 J16.1 J17.3 Q5.1 Q5.2 Q5.3 Q6.2 R84.1 TP25.2 TP30.2 U22.9 U22.15 U23.1 U24.1 U25.1 U26.1 | length 682.7
  Top Layer w20: U22.9@5671.93,227.41 5807.59,227.41 5838,197 J17.3@5838,120 ; U22.15@5671.93,527.41 5730.41,527.41 C64.1@5745,542 5746.5,543.5 C66.2@5800,543.5 5843.5,543.5 v2(5845,545) ; v2@6142.8,827.8 v2(6145,830) ; Q6.2@6207.4,202.76 6194.91,190.27 R84.1@6194.91,146.96 6197.95,150 v2(6240,150) ; v2(6225,355) U25.1@6225,390.32 ; U23.1@6225,569.68 v2(6225,605) ; U24.1@6230,879.68 v2(6230,910) ; v2(6230,950) U26.1@6230,985.32
I_BOOST_ADJ: R105.2 R107.2 TP17.1 U10.6 | length 577.1
  Top Layer w12: U10.6@3162.6,1392.2 3215.71,1392.2 R107.2@3230,1406.5 v2(3230,1450) ; R105.2@3388.5,1525 3338.5,1575 v2(3335,1575) 3390,1630 TP17.1@3480,1630
  Bottom Layer w12: v2(3230,1450) 3230,1555 3250,1575 v2(3335,1575)
NetC1_1: C1.1 R1.2 U1.5 | length 243.8
  Top Layer w10: U1.5@4540,1498.39 4540,1535
  Top Layer w16: 4540,1535 4560,1555 4610,1555 4635,1530 C1.1@4635,1491.5
  Top Layer w20: C1.1@4635,1491.5 R1.2@4690,1491.5
NetC2_1: C2.1 R2.2 U2.4 U2.5 | length 278.9
  Top Layer w10: R2.2@3808.5,2510 3808.5,2391.5 3822.41,2377.59 ; U2.5@3881.61,2352 3828,2352 3822.41,2357.59 3822.41,2377.59 ; U2.4@3881.61,2377.59 3822.41,2377.59
NetC4_1: C4.1 D3.3 L1.1 R4.2 R5.2 TP1.1 U3.5 | length 215.3
  Top Layer w10: U3.5@4379.37,1367.4 v2(4406.14,1367.4) 4436.74,1398 v2@4450,1398
  VCC w25: TP1.1@4200,1140 4200,1272
  other v2: 3975,1205 3950,1225 4450,1365 4443.37,1398 3915,1430 3915,1465 3915,1500 3975,1538.9 4015,1538.9 4055,1538.9 3915,1585 3915,1635 3915,1685 3975,1712.68 4020,1712.68 4063.66,1712.68 3915,1740 3915,1790
NetC4_2: C4.2 D2.1 U3.4 | length 230.2
  Top Layer w10: U3.4@4359.69,1367.4 4360.59,1366.5 4360.59,1329.41 4370,1320 ; D2.1@4449.47,1200 D2.1@4450,1200.53
  Top Layer w15: 4370,1320 4405,1320
  Top Layer w20: 4405,1320 4405.3,1319.7 4407.81,1319.7 4417.18,1310.33 4417.18,1307.82 4453,1272 4453,1226 4449.47,1222.47 D2.1@4449.47,1200
NetC7_1: C7.1 R4.1 R5.1 | length 151.8
  Top Layer w25: R5.1@4025,1360 R4.1@4025,1280 4056.5,1280 C7.1@4085,1308.5
NetC8_1: C8.1 J3.2 U3.10 | length 702.9
  Top Layer w10: v2(4262.6,1542.6) U3.10@4300.63,1542.6 ; v2(4540,1615) C8.1@4540,1658.5 4716.5,1658.5 4755,1620 J3.2@4838,1620
  Bottom Layer w10: v2(4262.6,1542.6) 4467.6,1542.6 v2(4540,1615)
NetC9_1: C9.1 Q1.3 R9.1 R10.1 R11.1 TP4.1 U3.1 | length 1481.5
  Top Layer w10: 4285,1351.77 U3.1@4300.63,1367.4 ; R10.1@4333.5,1115 4337,1111.5 C9.1@4337,1060 4337,1014.14 Q1.3@4356.14,995
  Top Layer w12: R9.1@3775,1618.5 3775,1590 3798.5,1566.5 R11.1@3798.5,1525 3798.5,1495.3 3860,1433.8 3860,1235 4030,1065 4055,1065 ; TP4.1@4055,960 4055,1065 ; C9.1@4337,1060 4060,1060 4055,1065
  Top Layer w15: 4285,1351.77 4285,1163.5 R10.1@4333.5,1115
NetC12_2: C12.2 C92.2 R125.1 U33.5 | length 166.5
  Top Layer w12: U33.5@4419.29,2775.59 4457.59,2775.59 C92.2@4470,2788 4523.5,2788 C12.2@4525,2786.5 R125.1@4580,2786.5
NetC15_1: C15.1 D23.1 J20.8 R128.2 | length 259.1
  Top Layer w12: D23.1@6138.15,2958.5 R128.2@6220,2958.5
  Top Layer w20: D23.1@6136.65,2960 6138.15,2958.5 6138.15,2948.85 6148.62,2938.38 C15.1@6148.62,2900 6165,2883.62 J20.8@6165,2805 J20.8@6157.59,2812.41
NetC16_1: C16.1 C17.2 R21.2 U8.5 | length 178.8
  Top Layer w12: U8.5@3437.4,905.87 3453,890.27
  Top Layer w16: C17.2@3453,845 3453,890.27
  Top Layer w20: R21.2@3453,733.5 C17.2@3453,845
NetC18_1: C18.1 R23.1 R26.1 | length 143.5
  Top Layer w25: C18.1@2875,501.5 R26.1@2875,570 R23.1@2950,570
NetC19_2: C19.2 R25.1 R27.2 U9.2 | length 274.5
  Top Layer w12: C19.2@3295,1368.5 3348.03,1368.5 R25.1@3355,1375.47 ; R27.2@3355,1321.5 R25.1@3355,1375.47 ; U9.2@3507.4,1362.8 3396.73,1362.8 3384.06,1375.47 R25.1@3355,1375.47
NetC22_2: C22.2 C23.2 R28.1 R29.1 U11.1 | length 271.3
  Top Layer w20: U11.1@2755.87,1747.4 2775.47,1747.4 2795.5,1767.43 C22.2@2795.5,1825 2795.5,1988.14 R29.1@2793.64,1990
NetC24_1: C24.1 R30.1 U10.3 | length 230.7
  Top Layer w12: C24.1@2920,1373.5 2938.7,1392.2 U10.3@2987.4,1392.2 3012.2,1392.2 3030,1410 3030,1513.5 R30.1@3028.5,1515
NetC29_1: C29.1 R33.2 U8.1 U10.4 | length 720.5
  Top Layer w12: U10.4@2987.4,1366.61 3159.02,1195 3435,1195 3461.5,1168.5 R33.2@3461.5,1130 C29.1@3461.5,1075 3461.5,1038.23 U8.1@3437.4,1014.13
NetC30_1: C30.1 R31.1 R32.1 | length 152.7
  Top Layer w20: R31.1@2800,1310 R32.1@2800,1225 2806.5,1218.5 C30.1@2865,1218.5
NetC31_2: C31.2 C33.2 R39.1 U13.5 | length 173.5
  Top Layer w20: R39.1@3475.31,613.5 3530.31,613.5 3581.82,613.5 C33.2@3585.31,617 3608.61,617 U13.5@3636.02,644.41
NetC32_2: C32.2 C34.2 R40.1 U14.5 | length 164.5
  Top Layer w12: R40.1@4085,638.5 4086.5,637 C34.2@4195,637 4202.59,629.41 U14.5@4245.71,629.41
NetC35_1: C35.1 R42.1 U13.4 | length 130.9
  Top Layer w12: R42.1@3576.81,730 3606.81,760 C35.1@3627.32,760 3636.02,751.29 U13.4@3636.02,695.59
NetC36_1: C36.1 R43.1 TP31.1 U14.4 | length 459.5
  Top Layer w12: 4221.5,745 C36.1@4252,745 4245.71,738.71 4245.71,710 ; U14.4@4245.71,680.59 4245.71,710 ; v5(4258.39,697.32) 4245.71,710 ; v5(4460,870) TP31.1@4460,895
  Bottom Layer w12: v5(4258.39,697.32) 4348.62,697.32 4460,808.7 v5(4460,870) v5@4460,880
NetC37_2: C37.2 R48.2 R52.2 R54.1 U13.3 | length 222
  Top Layer w12: U13.3@3724.61,695.59 3779.25,695.59 3780.31,694.53 3943.35,694.53 R48.2@3945.31,696.5
NetC38_2: C38.2 R49.2 R53.2 U14.3 | length 182.7
  Top Layer w10: U14.3@4334.29,680.59 4349.09,680.59 C38.2@4390,721.5 R53.2@4445,721.5 R49.2@4500,721.5
NetC41_1: C41.1 R55.2 U15.5 | length 242.5
  Top Layer w12: C41.1@2021.5,2880 2076.5,2880 R55.2@2080,2883.5 2100,2863.5 2100,2790 2090,2780 U15.5@2023.39,2780
NetC42_1: C42.1 R56.2 U16.5 | length 241.5
  Top Layer w12: R56.2@336.5,1775 358.8,1775 370.3,1786.5 C42.1@400,1786.5 400,1815 426.87,1841.87 478.13,1841.87 495,1825 U16.5@495,1793.39
NetC50_1: C50.1 R74.1 R76.2 U21.2 | length 412.1
  Top Layer w6: U21.2@3281.46,2234.88 3330.12,2234.88 3400,2165 C50.1@3431.38,2165 3453.03,2143.35 3505.54,2143.35 3505.89,2143 3524.11,2143 3524.46,2143.35 3576.97,2143.35 R76.2@3598.62,2165 R74.1@3646.38,2165
NetC51_1: C51.1 R75.1 R77.2 U21.3 | length 403.4
  Top Layer w6: U21.3@3281.46,2250.63 3354.37,2250.63 3395,2210 C51.1@3431.38,2210 3453.03,2188.35 3505.54,2188.35 3505.89,2188 3524.11,2188 3524.46,2188.35 3576.97,2188.35 R77.2@3598.62,2210 3600.79,2207.83 3622.17,2207.83 3625,2205 R75.1@3647.76,2205
NetC52_1: C52.1 R78.1 R79.2 U21.4 | length 517.8
  Top Layer w6: U21.4@3281.46,2266.38 3373.62,2266.38 3385,2255 C52.1@3431.38,2255 3453.38,2233 3524.11,2233 3524.46,2233.35 3576.97,2233.35 R79.2@3598.62,2255 v2(3635,2255) ; v2(3685,2340) 3686.38,2341.38 R78.1@3720,2341.38
  Bottom Layer w6: v2(3635,2255) 3635,2290 v2(3685,2340)
NetC53_1: C53.1 C54.2 R88.1 U21.34 | length 288.3
  Top Layer w8: R88.1@3095,1978.62 3116.4,1978.62 3123.72,1971.3 C53.1@3148.5,1971.3 3166.38,1989.17 C54.2@3166.38,2020 3166.38,2063.62 3161.38,2068.62 U21.34@3161.38,2193.54
NetC55_1: C55.1 U21.25 | length 133.9
  Top Layer w8: C55.1@2985,2325 C55.1@3000,2325 ; 3040,2320 3062.13,2297.87 U21.25@3088.54,2297.87
  Top Layer w12: 3020,2330 3030,2330 3040,2320
  Top Layer w20: C55.1@2985,2335 2990,2330 3020,2330
NetC56_1: C56.1 C57.2 R80.1 U21.17 | length 245.9
  Top Layer w8: 3155,2430 3161.38,2423.62 U21.17@3161.38,2386.46 ; C56.1@3158.62,2562.13 C56.1@3166.5,2570
  Top Layer w12: C57.2@3155,2516.38 C57.2@3158.62,2520
  Top Layer w20: 3155,2430 C57.2@3155,2516.38 ; C57.2@3158.62,2520 C56.1@3158.62,2562.13 ; C56.1@3166.5,2570 R80.1@3166.5,2625
NetC58_1: C58.1 C59.2 R81.1 U21.37 | length 303.3
  Top Layer w8: 3208.62,2121.02 U21.37@3208.62,2193.54
  Top Layer w12: 3208.62,2121.02 3220,2109.64 3266.38,2063.27 C59.2@3266.38,2020
  Top Layer w20: C59.2@3266.38,2020 3268.5,2017.87 C58.1@3268.5,1970 R81.1@3268.5,1915
NetC60_1: C60.1 C61.2 R82.1 U21.27 | length 276.3
  Top Layer w8: C61.2@2927.13,2223.5 C61.2@2935,2231.38 ; 2996.38,2231.38 3031.38,2266.38 U21.27@3088.54,2266.38
  Top Layer w16: C61.2@2935,2231.38 2996.38,2231.38
  Top Layer w20: R82.1@2830,2223.5 C60.1@2885,2223.5 C61.2@2927.13,2223.5
NetC63_2: C63.2 C65.1 R138.1 U22.1 | length 191.3
  Top Layer w20: R138.1@5111.5,580 5153.5,580 C65.1@5170,596.5 5183.5,583 C63.2@5225,583 5230.59,577.41 U22.1@5288.07,577.41
NetC68_1: C68.1 L3.2 L4.1 R92.2 | length 978.4
  Top Layer w50: R92.2@5565,1837.91 5637.91,1837.91 5680,1880 5910,1880 ; L4.1@5965,1650.08 5965,1685 5932.09,1717.91 C68.1@5932.09,1765 5932.09,1857.91 5910,1880 ; L3.2@6265,1899.92 6245.08,1880 5910,1880
NetC70_1: C70.1 R91.1 | length 124.7
  Top Layer w50: C70.1@5863.43,2045 5867.91,2045 R91.1@5952.91,2130
NetC71_1: C71.1 R92.1 | length 126.9
  Top Layer w50: C71.1@5443.43,1965 5526.5,1965 5539.41,1952.09 R92.1@5565,1952.09
NetC72_1: C72.1 R93.1 | length 350.6
  Top Layer w50: R93.1@5572.91,1295 5572.91,1421.65 C72.1@5731.26,1580
NetC73_1: C73.1 D22.2 J20.2 J20.4 J20.6 R95.1 R102.1 U27.5 U27.6 U27.8 U27.17@5385,2355 | length 534.5
  Top Layer w12: R95.1@5205,2333.5 5213.7,2342.2 U27.5@5268.86,2342.2 5372.2,2342.2 U27.17@5385,2355 5385,2325 5325.43,2265.43 U27.8@5268.86,2265.43 ; U27.6@5268.86,2316.61 U27.17@5346.61,2316.61
  Top Layer w25: R102.1@5661.5,2285 v2(5710,2285) ; C73.1@5661.5,2345 v2(5710,2345)
  other v2: 5385,2505 5385,2545 5385,2585 5745,2720 5770,2720
  other v4: 5341.69,2329.41 5385,2329.41 5428.31,2329.41 5341.69,2380.59 5385,2380.59 5428.31,2380.59
  other v6: 5341.69,2278.23 5385,2278.23 5428.31,2278.23 5341.69,2431.77 5385,2431.77 5428.31,2431.77
NetC73_2: C73.2 U27.12 | length 98.5
  Top Layer w12: U27.12@5501.14,2342.2 5595.71,2342.2 C73.2@5598.5,2345
NetC74_2: C74.2 C75.2 R109.2 U28.7 | length 176
  Top Layer w12: U28.7@3604.69,1840.12 3604.69,1887.69 3608.5,1891.5 C75.2@3608.5,1950 3608.5,1982.01 R109.2@3631.5,2005
NetC76_2: C76.2 C77.2 R110.2 U28.1 | length 194.1
  Top Layer w12: R110.2@3356.5,1735 3413.5,1735 C77.2@3420,1728.5 3423.5,1732 C76.2@3475,1732 3543.51,1732 U28.1@3545.63,1729.88
NetC81_2: C81.2 C82.1 R113.1 R114.1 U29.1 | length 459.2
  Top Layer w8: R113.1@4946.5,1811.5 4940.31,1805.31 5090.31,1805.31 5133.5,1848.5 R114.1@5150,1848.5
  Top Layer w20: R113.1@4940,1811.5 4940,1865 4955,1880 C82.1@4993.5,1880 4993.5,1931.5 C81.2@4997,1935 5002.6,1940.6 U29.1@5002.6,1985.87
NetC83_2: C83.2 C85.1 R115.2 | length 116.2
  Top Layer w10: R115.2@5737.99,996.5 R115.2@5735,993.5 C83.2@5735,936.5 C85.1@5790,936.5
NetC85_2: C85.2 R118.1 R121.2 U31.8 | length 883.7
  Top Layer w10: R118.1@5135,839.53 5165.04,839.53 5177.01,851.5 R121.2@5215,851.5 v2(5215,890) 5272.82,890 5280,897.18 U31.8@5280,934.88 ; v2(5790,825) C85.2@5790,873.5
  Bottom Layer w10: v2(5215,890) 5285,820 5785,820 v2(5790,825)
NetC88_2: C88.2 U31.4 | length 94.4
  Top Layer w8: 5256.55,1067.93 5260.31,1064.17 U31.4@5260.31,1045.12
  Top Layer w10: C88.2@5230,1127 5230,1094.48 5256.55,1067.93
NetC90_1: C90.1 U32.3 | length 74.3
  Top Layer w10: C90.1@5061.5,1775 5073.39,1763.11 U32.3@5073.39,1705.59
NetC93_1: C93.1 R126.2 U33.4 | length 124.8
  Top Layer w12: U33.4@4419.29,2724.41 4437,2706.7 C93.1@4437,2670 4454,2653 4454,2617.5 R126.2@4451.5,2615
NetC94_2: C94.2 R13.1 R16.2 U33.3 | length 227.7
  Top Layer w12: R13.1@4185,2621.5 R16.2@4240,2621.5 C94.2@4295,2621.5 4330.71,2657.2 U33.3@4330.71,2724.41
NetC95_1: C95.1 J5.2 J6.4 J6.5 J6.6 J18.1 Q4.5 Q4.6 Q4.7 Q4.8 Q4.9@868.5,2485 TP27.1 | length 400
  Top Layer w100: J5.2@930,2145 J6.5@930,2345
  Bottom Layer w100: J5.2@930,2145 J6.5@930,2345
  other v4: 852.75,2446.61 888.38,2446.61 834.94,2485 870.57,2485 906.2,2485 852.75,2523.39 888.38,2523.39
NetC95_2: C95.2 R130.2 | length 95.2
  Top Layer w50: R130.2@727.09,2264 728.09,2263 C95.2@821.91,2263
NetD5_1: D5.1 R11.2 | length 61.2
  Top Layer w12: D5.1@3860,1585.53 3861.5,1584.04 R11.2@3861.5,1525
NetD6_1: D6.1 D6.2 L2.1 Q2.5 Q2.6 Q2.7 Q2.8 Q2.9@2754.61,1435 R23.2 R26.2 R31.2 R32.2 TP6.1 | length 181.5
  Top Layer w25: R23.2@2943.39,643.39 R23.2@2950,650
  Top Layer w30: D6.1@2771.22,643.39 R23.2@2943.39,643.39
  other v4: 2734.72,1396.61 2770.35,1396.61 2716.91,1435 2752.54,1435 2788.17,1435 2734.72,1473.39 2770.35,1473.39
NetD7_1: D7.1 R131.2 R132.2
  other v2: 1318,2426 1348,2426 1378,2426 1408,2426 1438,2426 1468,2426 1498,2426 1528,2426 1558,2426 1588,2426 1618,2426 1648,2426 1678,2426 1708,2426 1738,2426 1768,2426 1798,2426 1828,2426 1318,2456 1348,2456 1378,2456 1408,2456 1438,2456 1468,2456 1498,2456 1528,2456 1558,2456 1588,2456 1618,2456 1648,2456 1678,2456 1708,2456 1738,2456 1768,2456 1798,2456 1828,2456 1318,2486 1348,2486 1378,2486 1408,2486 1438,2486 1468,2486 1498,2486 1528,2486 1558,2486 1588,2486 1618,2486 1648,2486 1678,2486 1828,2486 1348,2516 1378,2516 1408,2516 1438,2516 1618,2516 1648,2516 1678,2516 1828,2516 1348,2546 1378,2546 1408,2546 1438,2546 1618,2546 1648,2546 1678,2546 1828,2546 1348,2576 1378,2576 1408,2576 1438,2576 1618,2576 1648,2576 1678,2576 1828,2576 1348,2606 1378,2606 1408,2606 1438,2606 1618,2606 1648,2606 1678,2606 1828,2606 1378,2636 1408,2636 1438,2636 1618,2636 1648,2636 1678,2636 1828,2636 1408,2666 1438,2666 1618,2666 1648,2666 1678,2666 1828,2666 1438,2696 1468,2696 1498,2696 1528,2696 1558,2696 1588,2696 1618,2696 1648,2696 1678,2696 1828,2696 1468,2726 1498,2726 1528,2726 1558,2726 1588,2726 1618,2726 1648,2726 1678,2726 1708,2726 1738,2726 1768,2726 1798,2726 1828,2726 1498,2756 1528,2756 1558,2756 1588,2756 1618,2756 1648,2756 1678,2756 1708,2756 1738,2756 1768,2756 1798,2756 1828,2756 1348,2786 1528,2786 1558,2786 1588,2786 1618,2786 1648,2786 1678,2786 1708,2786 1738,2786 1768,2786 1798,2786 1828,2786 1348,2816 1378,2816 1528,2816 1558,2816 1588,2816 1618,2816 1648,2816 1678,2816 1708,2816 1738,2816 1768,2816 1798,2816 1828,2816 1318,2846 1348,2846 1378,2846 1408,2846 1438,2846 1468,2846 1498,2846 1528,2846 1558,2846 1588,2846 1618,2846 1648,2846 1678,2846 1708,2846 1738,2846 1768,2846 1798,2846 1828,2846
NetD7_2: D7.2 L6.2 | length 291.2
  Top Layer w50: D7.2@1244.51,2595 1248.66,2595 L6.2@1451.66,2798
NetD9_1: D9.1 L7.1 | length 2213.3
  VCC w100: v5@1100,2010 1100,1888.84 1081.46,1870.3 ccw(c1279,1575) 1236.02,1927.67
  other v2: 1220,1920 1220,1955 1220,1995 1220,2030
  other v5: 1070,2000 1100,2000 1130,2000 1070,2030 1100,2030 1130,2030
NetD9_2: D9.2 D9.3 D11.1
  other v1: 1865,1825 1825,1865 1865,1865 1825,1905 1865,1905 1825,1945 1865,1945 1425,1985 1465,1985 1505,1985 1545,1985 1585,1985 1625,1985 1665,1985 1705,1985 1745,1985 1785,1985 1825,1985 1865,1985 1905,1985 1945,1985 1985,1985 2025,1985 2065,1985 1305,2025 1345,2025 1385,2025 1425,2025 1465,2025 1505,2025 1545,2025 1585,2025 1625,2025 1665,2025 1705,2025 1745,2025 1785,2025 1825,2025 1865,2025 1905,2025 1945,2025 1985,2025 2025,2025 2065,2025 1305,2065 1345,2065 1385,2065 1425,2065 1465,2065 1505,2065 1545,2065 1585,2065 1625,2065 1665,2065 1705,2065 1745,2065 1785,2065 1825,2065 1865,2065 1905,2065 1945,2065 1985,2065 2025,2065 2065,2065 1345,2105 1385,2105 1425,2105 1465,2105 1505,2105 1545,2105 1585,2105 1625,2105 1665,2105 1705,2105 1745,2105 1785,2105 1825,2105 1865,2105 1905,2105 1945,2105 1985,2105 2025,2105 2065,2105 1345,2145 1385,2145 1425,2145 1465,2145 1505,2145 1545,2145 1585,2145 1625,2145 1665,2145 1705,2145 1745,2145 1785,2145 1825,2145 1865,2145 1905,2145 1945,2145 1985,2145 2025,2145 2065,2145 1345,2185 1385,2185 1425,2185 1465,2185 1505,2185 1545,2185 1585,2185 1625,2185 1665,2185 1705,2185 1745,2185 1785,2185 1825,2185 1865,2185 1905,2185 1945,2185 1985,2185 2025,2185 2065,2185 1345,2225 1385,2225 1425,2225 1465,2225 1505,2225 1545,2225 1585,2225 1625,2225 1665,2225 1705,2225 1745,2225 1785,2225 1825,2225 1865,2225 1905,2225 1945,2225 1985,2225 2025,2225 2065,2225 1265,2265 1305,2265 1345,2265 1385,2265 1425,2265 1465,2265 1505,2265 1545,2265 1585,2265 1625,2265 1665,2265 1705,2265 1745,2265 1785,2265 1825,2265 1865,2265 1905,2265 1945,2265 1985,2265 2025,2265 2065,2265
